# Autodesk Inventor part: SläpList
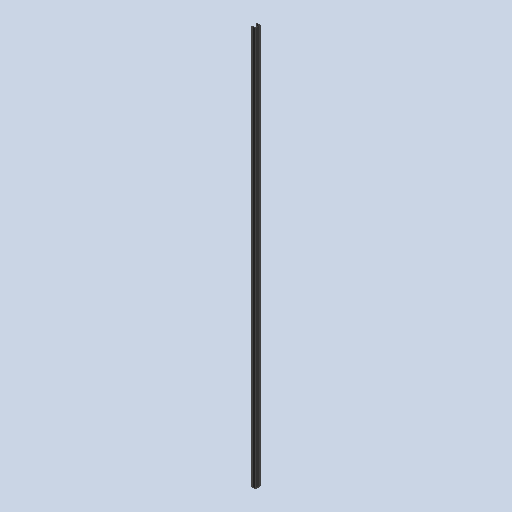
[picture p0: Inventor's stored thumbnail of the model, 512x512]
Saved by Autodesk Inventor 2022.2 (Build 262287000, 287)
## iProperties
Created: 2019-06
Part Number: SläpList
Material: Rubber
Document SubType Name: Modeling
Designer: cl
Density: 0.93 g/cm^3
Appearance: Rubber - Black
Author: cl
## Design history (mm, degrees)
sketch "Sketch1"
  geometry: L1 (0, 0)-(33, 0); L2 (33, 0)-(33, -2); L3 (33, -2)-(3, -2); L4 (3, -2)-(3, -48); L5 (3, -48)-(33, -48); L6 (33, -48)-(33, -50); L7 (33, -50)-(0, -50); L8 (0, -50)-(0, 0)
  constraints: 16 end point, 5 perpendicular, 2 point on line, 1 horizontal, 1 parallel
  dimensions: "d0" = 33 distance of L1.start L1.end; "d1" = 2 distance of L1.end L2.end; "d2" = 30 distance of L2.end L3.end; "d3" = 2 distance of L5.end L6.end; "d4" = 50 distance of L7.end L1.start
extrude "Extrusion1" new body sketch "Sketch1" distance "d5" = 4050 (computed from DagBredd_1); taper "d6" = 0 deg
body "Solid1"
other parameters: "BladBredd" = 987.5, "Fönsterhöjd" = 862
